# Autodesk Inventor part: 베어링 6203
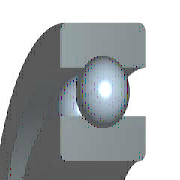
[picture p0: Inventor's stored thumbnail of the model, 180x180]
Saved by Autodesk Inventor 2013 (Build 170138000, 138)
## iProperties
IsCustomPart: 1
Created: 2012-02
Part Number: 베어링 6203
Material: 강철, 연강
Description: 깊은 그루브 볼 베어링
Document SubType Name: Modeling
Standard: KS B 2023
Designer: mduedu
Standards Organization: KS
Language: ko-KR
Size Designation: 6203 - 17 x 40 x 12
Categories: <MemberInstance><Categories><Category DisplayName="샤프트 부품" InternalName="7f7aeb1f-a693-4053-b835-cee3144e0d98" Mnemonic="SHFT"><Category DisplayName="베어링" Inter
Density: 7.86 g/cm^3
Mass: 64.9809 g
Surface Area: 64.3582 cm^2
Volume: 8.26729 cm^3
Author: mduedu
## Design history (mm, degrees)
sketch "스케치" dims "d0" = 5.98 (= -0.26 x WD + 0.26 x BD)
  geometry: L1 (3.01, 14.25)-(8.99, 14.25); L2 (6, 14.25)-(6, 11.26); L3 (6, 14.25)-(6, 17.24); L4 (3.778, 12.249)-(0, 12.249); L5 (0, 8.5)-(12, 8.5); L6 (3.778, 16.251)-(0, 16.251); L7 (0, 20)-(12, 20); L8 (12, 8.5)-(12, 12.249); L9 (8.222, 12.249)-(12, 12.249); L10 (8.222, 16.251)-(12, 16.251); L11 (12, 20)-(12, 16.251); L12 (-1.4, 0)-(8.4, 0) reference; L13 (0, -0.3)-(0, 5.3) reference
  constraints: 22 end point, 4 point on line, 2 collinear, 2 perpendicular, 2 symmetric about line, 1 midpoint, 1 parallel, 14 other
  dimensions: "d9" = 17 diameter of L5 L12 (= WD); "d11" = 40 diameter of L7 L12 (= BD); "d12" = 12 distance between parallel lines of L8 L13 (= KB); "d13" = 24.498 diameter of L9 L12 (= 0.326 x BD + 0.674 x WD)
revolve "본체" stored, may be unused: angle "d6" = 90 deg
revolve "볼" stored, may be unused: angle "d7" = 90 deg
pattern_circular "IDS_ARRAYBALL[SIMPL:T]" dims angle "d3" = 360 deg
body "Solid1"
fillet "모깎기1" dims "d1" = 0.6 (= KRS)
other parameters: "WD" = 17 [user parameter; used in 5 equation terms], "BD" = 40 [user parameter; used in 5 equation terms], "KB" = 12 [user parameter; used in 1 equation term], "KRS" = 0.6 [user parameter; used in 1 equation term], "d4" = 0, "d5" = 0, "d8" = 0, "d14" = 0, "d15" = 0, "BBA" = 0 [user parameter], "BC0" = 4750000 [user parameter], "BC" = 9560000 [user parameter], "WR" = 8.5 (= 0.5 x WD) [user parameter]
